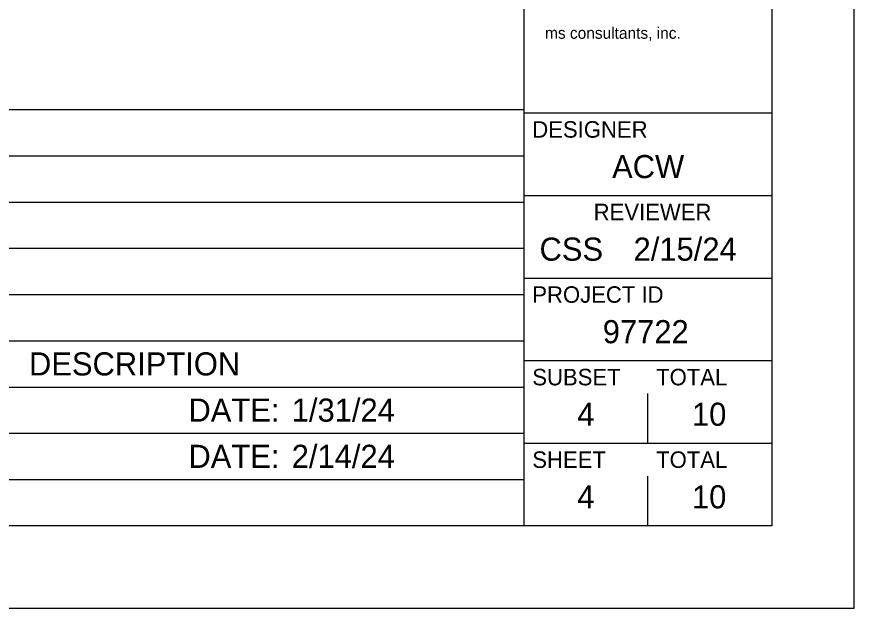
# Model space of a CAD drawing. Extents: x 0 to 34, y -1.2 to 22.
# Drawn here: x 28.93 to 34, y 0 to 3.58 of the extents above; entities that cross this region are included whole.
import ezdxf

# ---------------------------------------------------------------- set-up
doc = ezdxf.new("R2010")
doc.units = 0
for name, color, linetype in [('SH_Border', 7, 'Continuous'), ('SH_Cut_Line', 7, 'Continuous'), ('SH_Data', 7, 'Continuous'), ('SH_Text', 7, 'Continuous')]:
    doc.layers.add(name, color=color, linetype=linetype)

msp = doc.modelspace()

# ---------------------------------------------------------------- linework, layer by layer
at = {"layer": 'SH_Border'}
for p, q in [((32, 0.5), (32, 21.5)), ((32, 3), (33.5, 3)), ((32, 2.5), (33.5, 2.5)), ((32, 2), (33.5, 2)), ((32, 1.5), (33.5, 1.5)), ((32, 1), (33.5, 1))]:
    msp.add_line(p, q, dxfattribs=at)
msp.add_lwpolyline([(1.5, 21.5), (33.5, 21.5), (33.5, 0.5), (1.5, 0.5)], close=True, dxfattribs=at)
at = {"layer": 'SH_Cut_Line'}
msp.add_lwpolyline([(0, 0), (34, 0), (34, 22), (0, 22)], close=True, dxfattribs=at)
at = {"layer": 'SH_Data'}
for p, q in [((32.75, 1), (32.75, 1.3)), ((32.75, 0.5), (32.75, 0.8))]:
    msp.add_line(p, q, dxfattribs=at)
at = {"layer": 'SH_Text'}
for p, q in [((25.1966, 3.02), (32, 3.02)), ((25.1966, 2.74), (32, 2.74)), ((25.1966, 2.46), (32, 2.46)), ((25.1966, 2.18), (32, 2.18)), ((25.1966, 1.9), (32, 1.9)), ((25.1966, 1.62), (32, 1.62)), ((25.1966, 1.34), (32, 1.34)), ((25.1966, 1.06), (32, 1.06)), ((25.1966, 0.78), (32, 0.78)), ((32, 0.5), (32, 0.5))]:
    msp.add_line(p, q, dxfattribs=at)

# ---------------------------------------------------------------- texts
at = {"layer": 'SH_Border'}
msp.add_text('ms consultants, inc.', height=0.07, rotation=360, dxfattribs=at).set_placement((32.1273, 3.4489))
at = {"layer": 'SH_Data'}
for s, height, p in [('DESIGNER', 0.1, (32.05, 2.85)), ('ACW', 0.14, (32.5334, 2.605)), ('REVIEWER', 0.1, (32.4218, 2.35)), ('CSS', 0.14, (32.0938, 2.105)), ('2/15/24', 0.14, (32.6636, 2.105)), ('PROJECT ID', 0.1, (32.05, 1.85)), ('97722', 0.14, (32.4768, 1.605)), ('SUBSET', 0.1, (32.05, 1.35)), ('TOTAL', 0.1, (32.8, 1.35)), ('4', 0.14, (32.3223, 1.105)), ('10', 0.14, (33.0171, 1.105)), ('SHEET', 0.1, (32.05, 0.85)), ('TOTAL', 0.1, (32.8, 0.85)), ('4', 0.14, (32.3223, 0.605)), ('10', 0.14, (33.0171, 0.605))]:
    msp.add_text(s, height=height, dxfattribs=at).set_placement(p)
at = {"layer": 'SH_Text'}
for s, p in [('DESCRIPTION', (29.0016, 1.41)), ('DATE: ', (29.9673, 1.13)), ('1/31/24', (30.593, 1.13)), ('DATE: ', (29.9673, 0.85)), ('2/14/24', (30.593, 0.85))]:
    msp.add_text(s, height=0.14, dxfattribs=at).set_placement(p)

doc.saveas('drawing.dxf')
